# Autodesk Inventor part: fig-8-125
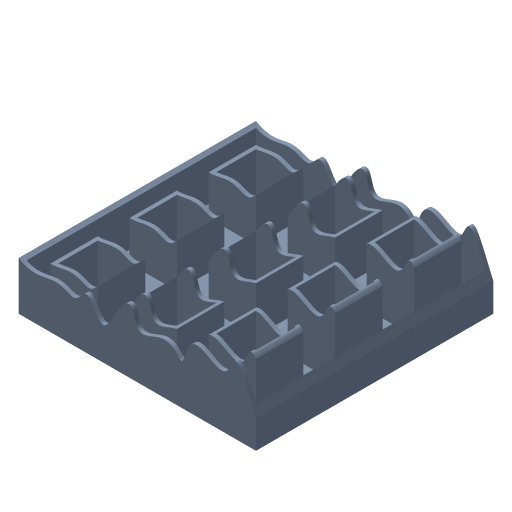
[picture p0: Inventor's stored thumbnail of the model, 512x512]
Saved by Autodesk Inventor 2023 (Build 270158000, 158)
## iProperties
Part Number: fig-8-125
Document SubType Name: Modeling
Created: 2002-12
Designer: deepak
Density: 1 g/cm^3
Material: Generic
Appearance: Light Steel Blue
Control State: 0
Master: False
Checked Out: False
Shininess: 64.0
Length Units: 11269
Angle Units: 11279
Time Units: 11290
Mass Units: 11283
Length Display Precision: 3
Angle Display Precision: 2
Compacted: True
Density: 0.0
Volumn: 0.0
Area: 0.0
PropertySet Name: Model Information
Author: deepak
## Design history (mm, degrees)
sketch "Sketch1"
  geometry: L1 (-32.188, 30.089)-(27.812, 30.089); L2 (27.812, 30.089)-(27.812, -29.911); L3 (27.812, -29.911)-(-32.188, -29.911); L4 (-32.188, -29.911)-(-32.188, 30.089)
  constraints: 8 end point, 2 parallel, 1 horizontal, 1 perpendicular
  dimensions: "d0" = 60 distance of L1.start L1.end; "d1" = 60 distance of L3.end L1.start
extrude "Extrusion1" new body sketch "Sketch1" stored distance "d2" = 20; taper "d3" = 0 deg
sketch "Sketch5"
  geometry: L1 (-27.812, 30.089)-(32.188, 30.089) reference; L2 (-27.812, -29.911)-(-27.812, 30.089) reference; L3 (-22.812, 25.089)-(-12.812, 25.089); L4 (-12.812, 25.089)-(-12.812, 15.089); L5 (-12.812, 15.089)-(-22.812, 15.089); L6 (-22.812, 15.089)-(-22.812, 25.089)
  constraints: 8 end point, 2 parallel, 1 horizontal, 1 perpendicular
  dimensions: "d8" = 10 distance of L3.start L3.end; "d9" = 10 distance of L5.end L3.start; "d10" = 5 distance between parallel lines of L2 L6; "d11" = 5 distance between parallel lines of L1 L3
extrude "Extrusion2" cut sketch "Sketch5" distance "d12" = 50; taper "d13" = 0 deg
pattern_linear "Rectangular Pattern1" dims "d16" = 20, "d19" = 20
shell "Shell2" dims "d21" = 1
sketch "Sketch2"
  geometry: 17 further points
  constraints: 17 other
extrude_surface "ExtrusionSrf1" sketch "Sketch2" dims "d4" = 70, "d5" = 0
split "Split2"
body "Solid1"
body "Srf1"
